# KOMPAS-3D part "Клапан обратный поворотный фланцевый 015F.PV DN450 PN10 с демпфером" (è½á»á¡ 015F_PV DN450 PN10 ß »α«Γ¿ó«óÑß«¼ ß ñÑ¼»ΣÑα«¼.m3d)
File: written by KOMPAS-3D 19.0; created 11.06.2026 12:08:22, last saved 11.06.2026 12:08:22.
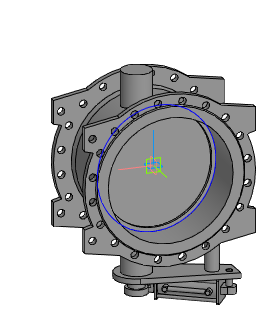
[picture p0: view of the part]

Document properties: Автор: Энергия; Полное имя файла: Z:\3.Личные\kachalov\001_3d для проектировщиков\5.5 Тип 015F.PV Клапан обратный поворотный с двумя эксцентриками\_stp_Клапан 015F.PV DN300-DN1200 с противовесом с демпфером\Клапан 015F_PV DN450 PN10 с противовесом с демпфером.m3d

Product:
- Part/product: Клапан обратный поворотный фланцевый 015F.PV DN450 PN10 с демпфером

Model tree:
1. Операция без истории:1
2. Сплайн:1
     Координата Y = 30; Координата Z = 225; Вес = 1; Координата X = 450; Координата Y = 89.2436; Координата Z = 225; Вес = 0.333333; Координата X = 450; Координата Y = 89.2436; Координата Z = -225; Вес = 0.333333; Координата Y = 30; Координата Z = -225; Вес = 1; Координата X = -450; Координата Y = -29.2436; Координата Z = -225; Вес = 0.333333; Координата X = -450; Координата Y = -29.2436; Координата Z = 225; Вес = 0.333333; Порядок = 4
